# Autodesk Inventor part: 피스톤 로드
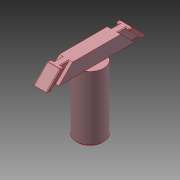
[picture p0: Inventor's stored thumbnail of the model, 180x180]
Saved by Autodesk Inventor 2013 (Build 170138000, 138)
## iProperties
Created: 2023-03
Part Number: 피스톤 로드
Material: 강철, 연강
Document SubType Name: Modeling
Designer: mdu-01
Density: 1 g/cm^3
Author: mdu-01
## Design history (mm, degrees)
sketch "스케치1"
  geometry: L1 (0, 0)-(0, 29); L2 (0, 29)-(8, 21); L3 (8, 21)-(8, 0); L4 (8, 0)-(0, 0); L5 (0, 26.172)-(8, 18.172); L6 (0, 21.929)-(8, 13.929)
  constraints: 12 end point, 4 point on line, 3 parallel, 1 perpendicular, 1 vertical
  dimensions: "d0" = 45 deg angle of L1 L2; "d1" = 29 distance of L1.start L1.end; "d2" = 8 distance between parallel lines of L3 L1; "d3" = 2 distance between parallel lines of L5 L2; "d4" = 3 distance between parallel lines of L6 L5
extrude "돌출1" new body sketch "스케치1" stored distance "d5" = 7.8; taper "d6" = 0 deg
extrude "돌출2" join sketch "스케치1" stored distance "d7" = 4; taper "d8" = 0 deg
fillet "모깎기5" dims "d31" = 0.5
sketch "스케치3"
  geometry: C1 r 8 at (-2, -21.929); 1 further point
  constraints: 1 centre point, 1 coincident
  dimensions: "d32" = 16 diameter of C1
extrude "돌출4" join sketch "스케치3" distance "d33" = 38; taper "d34" = 0 deg
chamfer "모따기2" distance "d35" = 1; stored, may be unused: second distance "d36" = 2, angle "d37" = 45 deg
hole "구멍2" diameter "d40" = 4.917; stored, may be unused: countersink angle "d44" = 90 deg, drill point angle "d46" = 118 deg; dims "d41" = 12, "d42" = 4, "d43" = 2, "d45" = 14, "d47" = 10, "d48" = 10
node "솔리드1"
pattern_circular "원형 패턴1" dims "d12" = 360 deg
